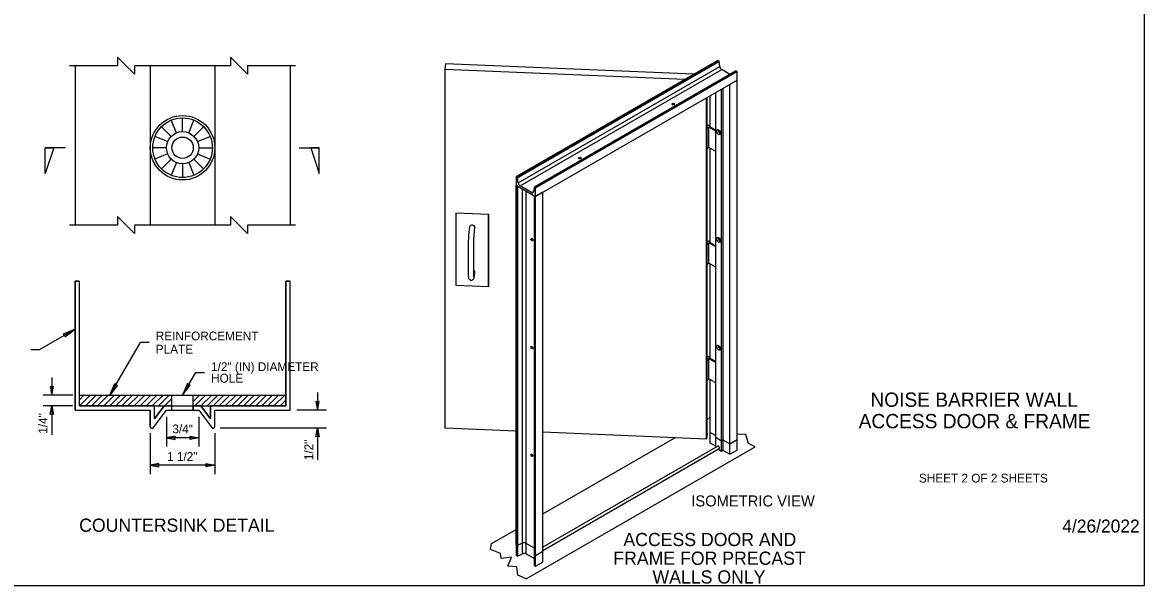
# Model space of a CAD drawing. Extents: x 99862 to 103151, y 100000 to 105076.
# Drawn here: x 101113 to 103151, y 103000 to 104023 of the extents above; entities that cross this region are included whole.
import ezdxf

# ---------------------------------------------------------------- set-up
doc = ezdxf.new("R2010")
doc.units = 0
for name, color, linetype in [('Level 1', 7, 'Continuous'), ('Level 15', 7, 'Continuous'), ('Level 18', 7, 'Continuous'), ('Level 20', 7, 'Continuous'), ('Level 5', 7, 'Continuous'), ('Level 62', 7, 'Continuous'), ('Level 9', 7, 'Continuous')]:
    doc.layers.add(name, color=color, linetype=linetype)

msp = doc.modelspace()

# ---------------------------------------------------------------- linework, layer by layer
at = {"layer": 'Level 1'}
msp.add_lwpolyline([(99862, 102999.5), (103151, 102999.5), (103151, 105075.5), (99862, 105075.5)], close=True, dxfattribs=at)
at = {"layer": 'Level 15'}
for p, q in [((101208.1, 103465.4), (101144.1, 103428.4)), ((101128.1, 103428.4), (101144.1, 103428.4)), ((101271.6, 103345.5), (101326.8, 103441.1)), ((101342.8, 103441.1), (101326.8, 103441.1)), ((101403.5, 103345.5), (101427.3, 103386.8)), ((101427.3, 103386.8), (101443.3, 103386.8)), ((101166, 103377.5), (101166, 103345.5)), ((101648.8, 103350.1), (101648.8, 103318.1)), ((101204, 103345.5), (101150, 103345.5)), ((101204, 103326), (101150, 103326)), ((101166, 103326), (101166, 103273.2)), ((101374.2, 103306.1), (101374.2, 103252.1)), ((101432.8, 103306.1), (101432.8, 103252.1)), ((101664.8, 103318.1), (101610.8, 103318.1)), ((101664.8, 103285.5), (101471.9, 103285.5)), ((101648.8, 103285.5), (101648.8, 103227.7)), ((101344.9, 103276.5), (101344.9, 103202.1)), ((101432.8, 103268.1), (101374.2, 103268.1)), ((101462.1, 103276.5), (101462.1, 103202.1)), ((101462.1, 103218.1), (101344.9, 103218.1))]:
    msp.add_line(p, q, dxfattribs=at)
for points in [[(101403.5, 103944.1), (101316.3, 103944.1), (101316.3, 103928.6), (101285.4, 103959.6), (101285.4, 103944.1), (101198.3, 103944.1)], [(101608.6, 103944.1), (101521.5, 103944.1), (101521.5, 103928.6), (101490.6, 103959.6), (101490.6, 103944.1), (101403.5, 103944.1)], [(101403.5, 103654.7), (101316.3, 103654.7), (101316.3, 103639.2), (101285.4, 103670.2), (101285.4, 103654.7), (101198.3, 103654.7)], [(101608.6, 103654.7), (101521.5, 103654.7), (101521.5, 103639.2), (101490.6, 103670.2), (101490.6, 103654.7), (101403.5, 103654.7)]]:
    msp.add_lwpolyline(points, dxfattribs=at)
for points in [[(101208.1, 103465.4), (101186.9, 103456.5), (101189.3, 103454.5), (101189.9, 103451.4)], [(101271.6, 103345.5), (101280.4, 103366.8), (101282.4, 103364.3), (101285.6, 103363.8)], [(101403.5, 103345.5), (101417.5, 103363.8), (101414.3, 103364.3), (101412.3, 103366.8)], [(101166, 103345.5), (101169, 103361.2), (101166, 103360.5), (101162.9, 103361.2)], [(101166, 103326), (101169, 103310.2), (101166, 103311), (101162.9, 103310.2)], [(101648.8, 103318.1), (101651.9, 103333.9), (101648.8, 103333.1), (101645.7, 103333.9)], [(101648.8, 103285.5), (101651.9, 103269.8), (101648.8, 103270.5), (101645.7, 103269.8)], [(101374.2, 103268.1), (101389.9, 103265.1), (101389.2, 103268.1), (101389.9, 103271.2)], [(101432.8, 103268.1), (101417, 103265.1), (101417.8, 103268.1), (101417, 103271.2)], [(101344.9, 103218.1), (101360.6, 103215.1), (101359.9, 103218.1), (101360.6, 103221.2)], [(101462.1, 103218.1), (101446.3, 103215.1), (101447.1, 103218.1), (101446.3, 103221.2)]]:
    msp.add_lwpolyline(points, close=True, dxfattribs=at)
at = {"layer": 'Level 18'}
for p, q in [((101208.1, 103944.1), (101208.1, 103654.7)), ((101344.9, 103944.1), (101344.9, 103654.7)), ((101462.1, 103944.1), (101462.1, 103654.7)), ((101598.8, 103944.1), (101598.8, 103654.7)), ((101881, 103947.7), (101879.8, 103937.6)), ((101879.8, 103937.6), (101879.8, 103285.4)), ((101879.8, 103937.6), (102315.9, 103919.5)), ((102332.3, 103928.9), (101881, 103947.7)), ((102009.5, 103742.6), (102375.5, 103953.9)), ((102011.5, 103741.4), (102377.6, 103952.7)), ((102012.2, 103740.3), (102378.3, 103951.6)), ((102013.2, 103731.2), (102379.3, 103942.5)), ((102016.7, 103725.6), (102382.8, 103937)), ((102377.6, 103952.7), (102375.5, 103953.9)), ((102379.3, 103942.5), (102378.3, 103951.6)), ((102397.5, 103928.5), (102382.8, 103937)), ((102408.3, 103934.7), (102042.3, 103723.4)), ((102042.8, 103723.3), (102408.8, 103934.7)), ((102044.8, 103722.1), (102410.9, 103933.5)), ((102044.8, 103706.8), (102410.9, 103918.1)), ((102397.6, 103910.4), (102410.9, 103918.1)), ((102410.9, 103933.5), (102408.8, 103934.7)), ((102410.9, 103918.1), (102410.9, 103933.5)), ((102410.9, 103264.9), (102410.9, 103918.1)), ((102382.5, 103262.8), (102382.5, 103901.7)), ((102385.2, 103903.3), (102385.2, 103264.4)), ((102397.6, 103257.2), (102397.6, 103910.4)), ((102355.3, 103265.7), (102355.3, 103886)), ((102356.5, 103275.8), (102356.5, 103886.7)), ((102362.2, 103832.8), (102362.2, 103890)), ((102371.9, 103268.9), (102371.9, 103895.6)), ((102292.5, 103874.3), (102292.5, 103874.3)), ((101392.2, 103822.1), (101382.7, 103845.1)), ((101403.5, 103824.4), (101403.5, 103849.3)), ((101414.7, 103822.1), (101424.2, 103845.1)), ((101376.4, 103806.3), (101353.4, 103815.8)), ((101382.7, 103815.8), (101365.1, 103833.4)), ((101424.2, 103815.8), (101441.8, 103833.4)), ((101430.5, 103806.3), (101453.5, 103815.8)), ((102356.6, 103831.7), (102355.3, 103820.9)), ((102355.3, 103784.2), (102355.3, 103820.9)), ((102356.6, 103795), (102356.6, 103831.7)), ((102371.9, 103825.2), (102359.5, 103832.3)), ((102359.5, 103795.6), (102359.5, 103832.3)), ((102360.6, 103833.7), (102360.6, 103833.9)), ((102360.6, 103833.7), (102371.9, 103827.2)), ((102374.7, 103828), (102374.7, 103828)), ((102379.7, 103819.4), (102379.7, 103819.4)), ((101374.2, 103795.1), (101349.3, 103795.1)), ((101432.8, 103795.1), (101457.7, 103795.1)), ((102356.6, 103795), (102355.3, 103784.2)), ((102371.9, 103788.4), (102359.5, 103795.6)), ((101376.4, 103783.8), (101353.4, 103774.3)), ((101382.7, 103774.3), (101365.1, 103756.7)), ((101424.2, 103774.3), (101441.8, 103756.7)), ((101430.5, 103783.8), (101453.5, 103774.3)), ((102362.2, 103622.6), (102362.2, 103794.1)), ((101392.2, 103768), (101382.7, 103745)), ((101403.5, 103765.8), (101403.5, 103740.9)), ((101414.7, 103768), (101424.2, 103745)), ((102009.5, 103742.6), (102009.5, 103727.2)), ((102011.5, 103741.4), (102009.5, 103742.6)), ((102013.2, 103731.2), (102012.2, 103740.3)), ((102009.5, 103074), (102009.5, 103727.2)), ((102011.5, 103726), (102009.5, 103727.2)), ((102009.5, 103727.2), (102044.8, 103706.8)), ((102011.5, 103072.8), (102011.5, 103726)), ((102012.8, 103072.7), (102012.8, 103725.2)), ((102037.5, 103713.6), (102016.7, 103725.6)), ((102021.2, 103076.4), (102021.2, 103720.4)), ((102027.8, 103076.1), (102027.8, 103716.6)), ((102037.5, 103713.6), (102041.1, 103715.7)), ((102042.1, 103723), (102041, 103715.1)), ((102044.8, 103722.1), (102042.8, 103723.3)), ((102044.8, 103706.8), (102044.8, 103722.1)), ((102058.1, 103714.4), (102044.8, 103706.8)), ((102058.1, 103061.3), (102058.1, 103714.4)), ((102042.5, 103708.1), (102042.5, 103055.2)), ((102042.8, 103054.7), (102042.8, 103707.9)), ((102044.8, 103706.8), (102042.8, 103707.9)), ((102044.8, 103053.6), (102044.8, 103706.8)), ((101899.7, 103676.2), (101899.7, 103676.5)), ((101959.6, 103674), (101899.7, 103676.5)), ((101899.7, 103676.2), (101899.7, 103545.6)), ((101959.5, 103673.7), (101899.7, 103676.2)), ((101959.5, 103673.7), (101959.6, 103674)), ((101959.5, 103543.1), (101959.5, 103673.7)), ((101959.6, 103543.4), (101959.6, 103674)), ((101924.6, 103651.1), (101923.9, 103645.3)), ((101933.8, 103644.1), (101934.6, 103649.9)), ((102374.7, 103632.1), (102374.7, 103632.1)), ((101922.4, 103616.9), (101922.4, 103567.9)), ((101932.4, 103567.9), (101932.4, 103616.9)), ((102036.9, 103630.1), (102036.9, 103630.1)), ((102039.4, 103625.8), (102039.4, 103625.8)), ((102356.6, 103621.5), (102355.3, 103610.7)), ((102356.6, 103584.7), (102356.6, 103621.5)), ((102371.9, 103614.9), (102359.5, 103622.1)), ((102359.5, 103585.3), (102359.5, 103622.1)), ((102360.6, 103623.5), (102360.6, 103623.6)), ((102360.6, 103623.5), (102371.9, 103617)), ((102379.7, 103623.4), (102379.7, 103623.4)), ((102355.3, 103573.9), (102355.3, 103610.7)), ((102356.6, 103584.7), (102355.3, 103573.9)), ((102371.9, 103578.2), (102359.5, 103585.3)), ((102362.2, 103412.3), (102362.2, 103583.8)), ((101208.1, 103318.1), (101208.1, 103552.5)), ((101208.1, 103552.5), (101216, 103552.5)), ((101216, 103551.8), (101215.2, 103552.5)), ((101216, 103326), (101216, 103552.5)), ((101591, 103552.5), (101598.8, 103552.5)), ((101591, 103326), (101591, 103552.5)), ((101598.8, 103318.1), (101598.8, 103552.5)), ((101933.8, 103562.5), (101934.6, 103568.2)), ((101899.7, 103545.6), (101959.5, 103543.1)), ((101959.5, 103543.1), (101959.6, 103543.4)), ((102036.9, 103434.1), (102036.9, 103434.1)), ((102039.4, 103429.8), (102039.4, 103429.8)), ((102374.7, 103436.1), (102374.7, 103436.1)), ((102379.7, 103427.4), (102379.7, 103427.4)), ((102356.6, 103411.2), (102355.3, 103400.4)), ((102356.6, 103374.5), (102356.6, 103411.2)), ((102371.9, 103404.7), (102359.5, 103411.8)), ((102359.5, 103375.1), (102359.5, 103411.8)), ((102360.6, 103413.2), (102360.6, 103413.4)), ((102360.6, 103413.2), (102371.9, 103406.7)), ((102355.3, 103363.7), (102355.3, 103400.4)), ((102356.6, 103374.5), (102355.3, 103363.7)), ((102371.9, 103367.9), (102359.5, 103375.1)), ((102362.2, 103277.6), (102362.2, 103373.6)), ((101216, 103345.5), (101591, 103345.5)), ((101216, 103326), (101235.5, 103345.5)), ((101216, 103337), (101224.4, 103345.5)), ((101216, 103326), (101352.7, 103326)), ((101216, 103326), (101591, 103326)), ((101227, 103326), (101246.5, 103345.5)), ((101238.1, 103326), (101257.6, 103345.5)), ((101249.1, 103326), (101268.6, 103345.5)), ((101260.2, 103326), (101279.7, 103345.5)), ((101271.2, 103326), (101290.7, 103345.5)), ((101282.2, 103326), (101301.8, 103345.5)), ((101293.3, 103326), (101312.8, 103345.5)), ((101304.3, 103326), (101323.9, 103345.5)), ((101315.4, 103326), (101334.9, 103345.5)), ((101326.4, 103326), (101346, 103345.5)), ((101337.5, 103326), (101357, 103345.5)), ((101348.5, 103326), (101368.1, 103345.5)), ((101352.7, 103302.5), (101352.7, 103326)), ((101352.7, 103302.5), (101370.3, 103326)), ((101359.6, 103326), (101379.1, 103345.5)), ((101370.3, 103326), (101436.7, 103326)), ((101370.6, 103326), (101383.9, 103339.2)), ((101381.7, 103326), (101383.9, 103328.2)), ((101383.9, 103318.1), (101383.9, 103345.5)), ((101423, 103318.1), (101423, 103345.5)), ((101423, 103334.1), (101434.4, 103345.5)), ((101425.9, 103326), (101445.4, 103345.5)), ((101436.7, 103326), (101454.2, 103302.5)), ((101436.9, 103326), (101456.5, 103345.5)), ((101448, 103326), (101467.5, 103345.5)), ((101454.2, 103326), (101591, 103326)), ((101454.2, 103302.5), (101454.2, 103326)), ((101459, 103326), (101478.6, 103345.5)), ((101470.1, 103326), (101489.6, 103345.5)), ((101481.1, 103326), (101500.7, 103345.5)), ((101492.2, 103326), (101511.7, 103345.5)), ((101503.2, 103326), (101522.8, 103345.5)), ((101514.3, 103326), (101533.8, 103345.5)), ((101525.3, 103326), (101544.8, 103345.5)), ((101536.4, 103326), (101555.9, 103345.5)), ((101547.4, 103326), (101566.9, 103345.5)), ((101558.5, 103326), (101578, 103345.5)), ((101569.5, 103326), (101589, 103345.5)), ((101580.6, 103326), (101591, 103336.4)), ((101208.1, 103318.1), (101344.9, 103318.1)), ((101344.9, 103288.5), (101344.9, 103318.1)), ((101350.5, 103286.6), (101374.2, 103318.1)), ((101374.2, 103318.1), (101432.8, 103318.1)), ((101432.8, 103318.1), (101456.4, 103286.6)), ((101462.1, 103288.5), (101462.1, 103318.1)), ((101462.1, 103318.1), (101598.8, 103318.1)), ((102009.5, 103280), (101879.8, 103285.4)), ((102355.3, 103265.7), (102058.1, 103278)), ((102356.5, 103275.8), (102355.3, 103265.7)), ((102362.2, 103277.6), (102371.9, 103272)), ((102371.9, 103268.9), (102382.5, 103262.8)), ((102371.9, 103250.3), (102371.9, 103268.9)), ((102385.2, 103264.4), (102382.5, 103262.8)), ((102385.2, 103264.4), (102397.6, 103257.2)), ((102385.2, 103264.4), (102385.2, 103245.3)), ((102397.6, 103257.2), (102410.9, 103264.9)), ((102410.9, 103245.8), (102410.9, 103264.9)), ((102376, 103252.6), (102058.1, 103069.1)), ((102058.1, 103063.4), (102378.5, 103248.3)), ((102376.6, 103247.2), (102382.5, 103243.7)), ((102382.5, 103243.7), (102382.5, 103262.8)), ((102382.5, 103243.7), (102385.2, 103245.3)), ((102385.2, 103245.3), (102397.6, 103238.1)), ((102397.6, 103238.1), (102397.6, 103257.2)), ((102397.6, 103238.1), (102410.9, 103245.8)), ((102039.4, 103233.8), (102039.4, 103233.8)), ((102011.5, 103072.8), (102009.5, 103074)), ((102009.5, 103074), (102009.5, 103054.9)), ((102011.5, 103053.7), (102011.5, 103072.8)), ((102021.2, 103076.4), (102012.8, 103072.7)), ((102012.8, 103053.6), (102012.8, 103072.7)), ((102021.2, 103057.3), (102021.2, 103076.4)), ((102042.5, 103067.6), (102027.8, 103076.1)), ((102027.8, 103057.1), (102027.8, 103076.1)), ((102058.1, 103061.3), (102044.8, 103053.6)), ((102058.1, 103042.2), (102058.1, 103061.3)), ((102009.5, 103054.9), (102011.5, 103053.7)), ((102012.8, 103053.6), (102021.2, 103057.3)), ((102027.8, 103057.1), (102042.5, 103048.6)), ((102042.5, 103055.2), (102042.5, 103036.1)), ((102044.8, 103053.6), (102042.8, 103054.7)), ((102042.8, 103035.7), (102042.8, 103054.7)), ((102044.8, 103034.5), (102044.8, 103053.6)), ((102044.8, 103034.5), (102058.1, 103042.2)), ((102042.8, 103035.7), (102044.8, 103034.5))]:
    msp.add_line(p, q, dxfattribs=at)
for points in [[(101293.3, 103326), (101282.2, 103326), (101271.2, 103326), (101260.2, 103326), (101249.1, 103326), (101238.1, 103326), (101227, 103326), (101216, 103326), (101216, 103337), (101216, 103345.5), (101216, 103551.8), (101215.2, 103552.5), (101208.1, 103552.5), (101208.1, 103318.1), (101344.9, 103318.1), (101344.9, 103288.5)], [(101462.1, 103288.5), (101462.1, 103318.1), (101598.8, 103318.1), (101598.8, 103552.5), (101591, 103552.5), (101591, 103345.5), (101591, 103336.4), (101591, 103326), (101580.6, 103326), (101569.5, 103326), (101558.5, 103326), (101547.4, 103326), (101536.4, 103326), (101525.3, 103326), (101514.3, 103326), (101503.2, 103326), (101492.2, 103326), (101481.1, 103326), (101470.1, 103326), (101459, 103326), (101454.2, 103326), (101454.2, 103302.5), (101436.7, 103326), (101425.9, 103326), (101423, 103326), (101423, 103318.1), (101432.8, 103318.1), (101456.4, 103286.6)], [(101350.5, 103286.6), (101374.2, 103318.1), (101383.9, 103318.1), (101383.9, 103326), (101381.7, 103326), (101370.6, 103326), (101370.3, 103326), (101352.7, 103302.5), (101352.7, 103326), (101348.5, 103326), (101337.5, 103326), (101326.4, 103326), (101315.4, 103326), (101304.3, 103326), (101293.3, 103326)], [(102371.9, 103252.9), (102362.2, 103258.5), (102362.2, 103277.6)]]:
    msp.add_lwpolyline(points, dxfattribs=at)
for radius in [58.6, 54.2, 29.3, 19.5]:
    msp.add_circle((101403.5, 103795.1), radius, dxfattribs=at)
for centre, radius, start, end in [((101348, 103288.5), 3.12, 180, 323.1301), ((101348, 103288.5), 3.12, 180, 323.1301), ((101458.9, 103288.5), 3.12, 216.8699, 0), ((101458.9, 103288.5), 3.13, 216.8699, 0)]:
    msp.add_arc(centre, radius, start, end, dxfattribs=at)
for centre, major_axis, ratio, start_param, end_param in [((102377.6, 103951.9), (0.5, -0.866), 0.57735, 0.922861, 2.356194), ((102382.8, 103941.1), (-2.5, 4.33), 0.57735, 0.922861, 2.356194), ((102408.8, 103933.9), (-0.5, 0.866), 0.57735, 5.497787, 6.283223), ((102295, 103871.6), (2.5, 0), 0.57735, 1.166143, 1.97545), ((102356.9, 103833.9), (3.75, 0), 0.57735, 6.227515, 7.949711), ((102356.9, 103833.9), (3.75, 0), 0.57735, 4.616659, 4.64064), ((102356.9, 103833.9), (3.75, 0), 0.57735, 4.64064, 5.497787), ((102356.9, 103833.9), (3.75, 0), 0.57735, 5.497787, 6.227515), ((102379.9, 103825.2), (2.5, -4.33), 0.57735, 3.700583, 5.724195), ((102379.9, 103825.2), (1.25, -2.17), 0.57735, 3.50296, 5.921818), ((102356.9, 103797.1), (3.75, 0), 0.57735, 4.64064, 5.497787), ((102125.3, 103773.6), (2.5, 0), 0.57735, 1.166143, 1.97545), ((102011.5, 103740.6), (0.5, -0.866), 0.57735, 0.922861, 2.356194), ((102016.7, 103729.7), (-2.5, 4.33), 0.57735, 0.922861, 2.356194), ((102037.5, 103717.7), (2.5, -4.33), 0.57735, 5.497792, 6.931121), ((102042.8, 103722.5), (-0.5, 0.866), 0.57735, 5.497787, 6.931121), ((101929.6, 103650.5), (4.96, -0.62), 0.814396, 0, 3.141568), ((101929.6, 103650.5), (4.96, -0.62), 0.814396, 3.141568, 3.141617), ((102379.9, 103629.3), (2.5, -4.33), 0.57735, 3.700583, 5.724195), ((101927.4, 103616.9), (5, 0), 0.57735, 6.211436, 6.283185), ((102040.5, 103629.3), (-1.25, 2.17), 0.57735, 1.166143, 1.97545), ((102356.9, 103623.6), (3.75, 0), 0.57735, 6.227515, 7.949711), ((102356.9, 103623.6), (3.75, 0), 0.57735, 4.616659, 4.64064), ((102356.9, 103623.6), (3.75, 0), 0.57735, 4.64064, 5.497787), ((102356.9, 103623.6), (3.75, 0), 0.57735, 5.497787, 6.227515), ((102379.9, 103629.3), (1.25, -2.17), 0.57735, 3.50296, 5.921818), ((101929.6, 103568.8), (4.96, -0.62), 0.814396, 6.283185, 7.346876), ((102356.9, 103586.9), (3.75, 0), 0.57735, 4.64064, 5.497787), ((101927.4, 103567.9), (5, 0), 0.57735, 3.141593, 3.143635), ((101928.9, 103563.1), (4.96, -0.62), 0.814396, 6.283185, 6.283208), ((102040.5, 103433.3), (-1.25, 2.17), 0.57735, 1.166143, 1.97545), ((102379.9, 103433.3), (2.5, -4.33), 0.57735, 3.700583, 5.724195), ((102379.9, 103433.3), (1.25, -2.17), 0.57735, 3.50296, 5.921818), ((102356.9, 103413.4), (3.75, 0), 0.57735, 6.227515, 7.949711), ((102356.9, 103413.4), (3.75, 0), 0.57735, 4.616659, 4.64064), ((102356.9, 103413.4), (3.75, 0), 0.57735, 4.64064, 5.497787), ((102356.9, 103413.4), (3.75, 0), 0.57735, 5.497787, 6.227515), ((102356.9, 103376.6), (3.75, 0), 0.57735, 4.64064, 5.497787), ((102377.3, 103250.5), (-1.25, 2.17), 0.57735, 3.141569, 6.283185), ((102040.5, 103237.3), (-1.25, 2.17), 0.57735, 1.166143, 1.97545), ((102012.2, 103073.2), (1, 0), 0.57735, 3.926991, 5.360325), ((102012.2, 103073.2), (1, 0), 0.57735, 3.926991, 5.360325), ((102024.2, 103074.1), (-5, 0), 0.57735, 3.926991, 5.360325), ((102012.2, 103054.1), (1, 0), 0.57735, 3.926991, 5.360325), ((102024.2, 103055), (-5, 0), 0.57735, 3.926991, 5.360325), ((102043.5, 103055.2), (-1, 0), 0.57735, 6.283185, 7.068583), ((102043.5, 103036.1), (-1, 0), 0.57735, 6.283185, 7.068583)]:
    msp.add_ellipse(centre, major_axis=major_axis, ratio=ratio, start_param=start_param, end_param=end_param, dxfattribs=at)
for centre, major_axis in [((102295, 103874.3), (-2.5, 0)), ((102377.2, 103823.7), (-2.5, 4.33)), ((102125.3, 103776.3), (-2.5, 0)), ((102377.2, 103627.7), (-2.5, 4.33)), ((102038.2, 103627.9), (1.25, -2.17)), ((102038.2, 103432), (1.25, -2.17)), ((102377.2, 103431.8), (-2.5, 4.33)), ((102038.2, 103236), (1.25, -2.17))]:
    msp.add_ellipse(centre, major_axis=major_axis, ratio=0.57735, dxfattribs=at)
for points in [[(101923.9, 103645.3), (101923.6, 103642.8), (101922.8, 103633.9), (101922.4, 103622.2), (101922.4, 103616.9)], [(101932.4, 103616.9), (101932.4, 103620.1), (101932.7, 103630.4), (101933.4, 103640.6), (101933.8, 103644.1)], [(101922.4, 103567.9), (101922.5, 103564.8), (101922.5, 103561.4), (101922.9, 103559.1), (101923.3, 103557.4), (101924.8, 103555.2), (101927.9, 103554.1), (101931.3, 103555.1), (101933, 103557.8), (101933.3, 103559.5), (101933.7, 103561.2), (101933.8, 103562.5)], [(101932.7, 103561), (101932.7, 103561), (101932.5, 103561.8), (101932.5, 103564.8), (101932.4, 103567.9)]]:
    msp.add_open_spline(points, degree=3, dxfattribs=at)
at = {"layer": 'Level 5'}
for p, q in [((102356.5, 103302), (102362.2, 103305.2)), ((102058.1, 103129.7), (102297.8, 103268.1)), ((102027.5, 103011.6), (102443.7, 103251.8)), ((101964.9, 103075.9), (102009.5, 103101.6))]:
    msp.add_line(p, q, dxfattribs=at)
for points in [[(102443.7, 103251.8), (102431.7, 103257.9), (102426.8, 103274.1), (102410.9, 103274.9)], [(102027.5, 103011.6), (102012.6, 103018.3), (102010.7, 103033.8), (101994.5, 103034.6), (102001.3, 103051.1), (101982.2, 103048.9), (101981.1, 103057.6), (101963.1, 103064.9), (101964.9, 103075.9)]]:
    msp.add_lwpolyline(points, dxfattribs=at)
at = {"layer": 'Level 9'}
for p, q in [((101190.7, 103795.1), (101154.2, 103795.1)), ((101615.3, 103795.1), (101651.9, 103795.1))]:
    msp.add_line(p, q, dxfattribs=at)
for points in [[(101169.7, 103795.1), (101154.1, 103748.2), (101154.1, 103795.1)], [(101636.3, 103795.1), (101651.9, 103748.2), (101651.9, 103795.1)]]:
    msp.add_lwpolyline(points, close=True, dxfattribs=at)

# ---------------------------------------------------------------- texts
at = {"layer": 'Level 15'}
msp.add_text('4/26/2022', height=23.62, dxfattribs=at).set_placement((103001.6, 103095.8))
at = {"layer": 'Level 20'}
for s, rotation, p in [('REINFORCEMENT', 360, (101354.8, 103445.1)), ('PLATE', 360, (101354.8, 103421.1)), ('1/4"', 90, (101158, 103275.3)), ('3/4"', 360, (101385, 103276.1)), ('1/2"', 90, (101640.8, 103227.4)), ('1 1/2"', 360, (101375.4, 103226.1))]:
    msp.add_text(s, height=16, rotation=rotation, dxfattribs=at).set_placement(p)
for s, height, p in [('1/2" (IN) DIAMETER', 16, (101455.3, 103389.2)), ('HOLE', 16, (101455.3, 103368.4)), ('ISOMETRIC VIEW', 20, (102327.6, 103143.3)), ('COUNTERSINK DETAIL', 24, (101215.7, 103097.2)), ('ACCESS DOOR AND', 24, (102204.3, 103071.2)), ('FRAME FOR PRECAST', 24, (102186, 103037.2)), ('WALLS ONLY', 24, (102257.2, 103003.2))]:
    msp.add_text(s, height=height, dxfattribs=at).set_placement(p)
at = {"layer": 'Level 62'}
for s, height, p in [('NOISE BARRIER WALL', 26, (102653, 103324.3)), ('ACCESS DOOR & FRAME', 26, (102631.7, 103285.3)), ('SHEET 2 OF 2 SHEETS', 16, (102741.1, 103186.8))]:
    msp.add_text(s, height=height, dxfattribs=at).set_placement(p)

doc.saveas('drawing.dxf')
